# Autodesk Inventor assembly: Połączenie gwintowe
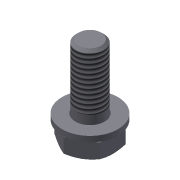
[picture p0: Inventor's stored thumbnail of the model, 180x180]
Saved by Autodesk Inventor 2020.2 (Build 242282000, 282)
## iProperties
Created: 2010-09
Part Number: Połączenie gwintowe
Document SubType Name: Assembly
Designer: F.Stasiak
ClientObjectVersion: 1
Manager: www.cadconsulting.pl
Company: Fabian Stasiak CAD Consulting
Author: F.Stasiak
Subject: Zbiór ćwiczeń. Autodesk Inventor 2020. Kurs podstawowy
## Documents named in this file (3)
- C:\2020_Kurs_podstawowy\R9 Zarządzanie plikami\369-000\Design Accelerator\Połączenie gwintowe3.iam
- C:\2020_Kurs_podstawowy\Zasoby\Content Center Files\pl-PL\ISO 7089\ISO 7089 - 8 - 140 HV(1).ipt
- C:\2020_Kurs_podstawowy\Zasoby\Content Center Files\pl-PL\ISO 4017(1)\ISO 4017 - M8 x 20ISO.ipt
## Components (2 placed, 2 different names)
1. ISO 7089 8 - 140 HV:1
2. ISO 4017 M8 x 20:1
